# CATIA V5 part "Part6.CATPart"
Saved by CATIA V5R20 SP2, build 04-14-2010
Part number: Part4.1
Bounding box of the stored display mesh (mm): x 0 to 40, y -14.119 to 167.761, z 82.437 to 124.337
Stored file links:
  E:\Ehsan\Amoozesh\CATIA\CATIA Course\Basic\Exercises\Assembly\6\Part6.CATPart
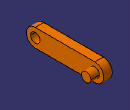
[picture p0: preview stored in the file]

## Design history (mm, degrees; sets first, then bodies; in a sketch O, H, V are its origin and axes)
Body1 (main body)
  Sketch1 on yz-plane, origin (0, 0, 0), H (0, 1, 0), V (0, 0, 1)
    construction line L1 (6.8209, 103.3865) -> (146.8209, 103.3865)
    line L2 (6.8209, 124.3365) -> (146.8209, 124.3365)
    line L3 (146.8209, 82.4365) -> (6.8209, 82.4365)
    arc A1 centre (146.8209, 103.3865) radius 20.95 from (146.8209, 124.3365) to (146.8209, 82.4365) cw
    arc A2 centre (6.8209, 103.3865) radius 20.95 from (6.8209, 82.4365) to (6.8209, 124.3365) cw
    circle A3 centre (146.8209, 103.3865) radius 11.04
    circle A4 centre (6.8209, 103.3865) radius 11.04
  MultiPad1: profile Sketch1, domains (length 20; length 0; length 40)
